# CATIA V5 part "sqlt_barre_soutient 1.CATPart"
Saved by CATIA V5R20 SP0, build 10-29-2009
Part number: sqlt_barre_soutient 1
Publications: "longeur_barre", "Plan.2", "Point.2", "Point.3", "Droite.1", "Plan.3"
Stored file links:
  D:\ecole\thinkmotion\sqlt_barre_soutient 1.CATPart
  D:\ecole\thinkmotion\sqlt_eolienne.CATProduct
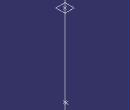
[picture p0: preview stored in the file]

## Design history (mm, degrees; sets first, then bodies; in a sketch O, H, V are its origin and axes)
Parameters
  longeur_barre = 1000 mm {= External.longueur_barre_principale}
External parameters (linked from other documents)
  `External.diamètre_trou` = 40 mm
  External.longueur_barre_principale = 1000 mm
Set1 "sqlt_poulie_principale"
  Plane1 "plan de bout de barre": type Offset, RefPlane xy-plane, Offset 0
  Point1: (0, 0, 0)
  Point2: (0, 0, 1000 {= longeur_barre})
  Line1 "Axe de rotation barre": type PtPt, FirstPoint Point1, SecondPoint Point2
  Plane2 "Plan de bout de barre": type Offset, RefPlane Plane1, Offset 1000 {= longeur_barre}
  Point3: (0, 20 {= `External.diamètre_trou` /2}, 0)
  Plane3 "plan de dessin": type Offset, RefPlane yz-plane, Offset 0
  Plane4: type Offset, RefPlane zx-plane, Offset 0
Body1 (main body)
